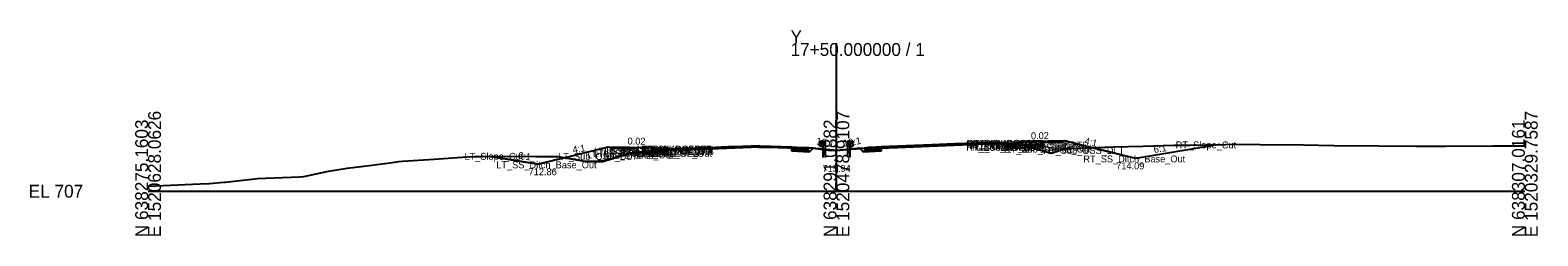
# Model space of a CAD drawing. Extents: x -26 to 303, y -10 to 5039.
# Drawn here: x -25.7 to 302.8, y 990.3 to 1035 of the extents above; entities that cross this region are included whole.
import ezdxf

# ---------------------------------------------------------------- set-up
doc = ezdxf.new("R2010")
doc.units = 0
for name, color, linetype in [('Default', 7, 'Continuous'), ('Exist Cross Section Cell', 7, 'Continuous'), ('Exist XS Center Line Elevation Label', 7, 'Continuous'), ('Exist XS Ground Line', 7, 'Continuous'), ('Prop CMT Pvmt Course 1', 7, 'Continuous'), ('Prop CMT Pvmt Course 2', 7, 'Continuous'), ('Prop CMT Pvmt Course 3', 7, 'Continuous'), ('Prop CMT Pvmt Surface', 7, 'Continuous'), ('Prop CMT Pvmt Surface Shoulder', 7, 'Continuous'), ('Prop CMT Shld Paved Course 1', 7, 'Continuous'), ('Prop CMT Shld Paved Course 2', 7, 'Continuous'), ('Prop CMT Shld Paved Course 3', 7, 'Continuous'), ('Prop CMT Slope Grass', 7, 'Continuous'), ('Prop CMT Subgrade Earthwork', 7, 'Continuous'), ('Prop Conc 4in Sidewalk', 7, 'Continuous'), ('Prop XS Ditch Standard Text', 7, 'Continuous'), ('Prop XS Earthwork Shape', 7, 'Continuous'), ('Prop XS Side Slope Text', 7, 'Continuous'), ('Scratch_Level_0', 7, 'Continuous'), ('Typical Curb CELL', 7, 'Continuous'), ('Typical Guardrail CELL', 7, 'Continuous'), ('Typical Shoulder Slope Information CELL', 7, 'Continuous')]:
    doc.layers.add(name, color=color, linetype=linetype)

# ---------------------------------------------------------------- blocks, each defined once
blk = doc.blocks.new('2_6 CURB RIGHT')
at = {"layer": 'Typical Curb CELL'}
for p, q in [((0, -0.58), (0, 0)), ((0, 0), (1.75, -0.07)), ((2, 0.17), (2, 0.18)), ((2.5, 0.42), (2.24, 0.42)), ((2.31, 0.08), (2.33, -0.01)), ((2.46, 0.04), (2.31, 0.08)), ((2.33, -0.01), (2.46, 0.04)), ((2.5, -0.58), (2.5, 0.42)), ((2.5, -0.58), (0, -0.58)), ((0.26, -0.34), (0.35, -0.22)), ((0.38, -0.34), (0.26, -0.34)), ((0.35, -0.22), (0.38, -0.34)), ((1.03, -0.39), (1.09, -0.28)), ((1.19, -0.36), (1.03, -0.39)), ((1.09, -0.28), (1.19, -0.36)), ((1.51, -0.34), (1.6, -0.22)), ((1.63, -0.34), (1.51, -0.34)), ((1.6, -0.22), (1.63, -0.34)), ((2.27, -0.39), (2.34, -0.28)), ((2.44, -0.36), (2.27, -0.39)), ((2.34, -0.28), (2.44, -0.36))]:
    blk.add_line(p, q, dxfattribs=at)
for centre in [(2.27, 0.34), (2.43, 0.12), (2.49, 0.31), (0.01, -0.55), (0.02, -0.25), (0.03, -0.15), (0.07, -0.39), (0.09, -0.18), (0.17, -0.34), (0.2, -0.06), (0.22, -0.58), (0.3, -0.14), (0.34, -0.04), (0.38, -0.51), (0.49, -0.1), (0.52, -0.21), (0.59, -0.53), (0.67, -0.29), (0.69, -0.12), (0.7, -0.45), (0.71, -0.07), (0.76, -0.56), (0.79, -0.26), (0.93, -0.5), (0.97, -0.1), (1.09, -0.15), (1.11, -0.54), (1.26, -0.55), (1.27, -0.25), (1.28, -0.15), (1.32, -0.39), (1.34, -0.18), (1.42, -0.34), (1.45, -0.1), (1.47, -0.58), (1.54, -0.14), (1.63, -0.51), (1.74, -0.1), (1.77, -0.21), (1.84, -0.53), (1.92, -0.29), (1.94, -0.12), (1.95, -0.45), (1.96, -0.07), (2.01, -0.56), (2.04, -0.26), (2.18, -0.5), (2.22, -0.1), (2.34, -0.15), (2.35, -0.54)]:
    blk.add_circle(centre, 0.00802, dxfattribs=at)
for centre, start, end in [((1.76, 0.17), 267.6155, 0), ((2.24, 0.18), 90, 180)]:
    blk.add_arc(centre, 0.24, start, end, dxfattribs=at)

msp = doc.modelspace()

# ---------------------------------------------------------------- linework, layer by layer
at = {"layer": 'Exist Cross Section Cell'}
for p, q in [((150, 1000), (150, 1032.23)), ((0, 1000), (150, 1000)), ((150, 1000), (300, 1000))]:
    msp.add_line(p, q, dxfattribs=at)
at = {"layer": 'Exist XS Ground Line'}
msp.add_lwpolyline([(0, 1001.13), (11.32, 1001.62), (13.39, 1001.69), (16.48, 1001.95), (16.86, 1001.98), (23.3, 1002.71), (23.79, 1002.76), (33, 1003.14), (33.92, 1003.18), (39.29, 1004.39), (43.39, 1004.99), (46.42, 1005.39), (52.17, 1006.11), (54.68, 1006.47), (55.45, 1006.53), (62.37, 1006.98), (69.47, 1007.46), (71, 1007.58), (73.03, 1007.58), (78.32, 1007.61), (84.6, 1007.54), (89.39, 1007.52), (93.79, 1006.76), (95.25, 1006.5), (96.1, 1006.47), (99.1, 1006.49), (102.64, 1007.54), (104.42, 1008.15), (106.25, 1008.4), (110.51, 1008.99), (111.2, 1009.02), (112.34, 1009.06), (112.69, 1009.07), (114.56, 1009.17), (114.9, 1009.17), (117.35, 1009.26), (117.71, 1009.28), (119.87, 1009.36), (120.52, 1009.39), (122.37, 1009.46), (123.87, 1009.52), (124.88, 1009.56), (126.32, 1009.63), (126.93, 1009.65), (128.26, 1009.64), (129.89, 1009.64), (131.76, 1009.63), (132.42, 1009.63), (132.94, 1009.62), (135.23, 1009.6), (137.49, 1009.58), (139.15, 1009.56), (142.59, 1009.45), (144.9, 1009.37), (147.17, 1009.11), (148.87, 1008.87), (150, 1008.94), (153.3, 1009.16), (155.34, 1009.32), (157.77, 1009.45), (161.68, 1009.64), (162.06, 1009.65), (162.83, 1009.67), (165.12, 1009.78), (165.57, 1009.8), (167.64, 1009.91), (168.37, 1009.95), (170.15, 1010.04), (171.19, 1010.1), (172.65, 1010.18), (173.3, 1010.21), (173.72, 1010.24), (174.51, 1010.25), (175.15, 1010.26), (176.79, 1010.3), (177.66, 1010.32), (179.6, 1010.36), (180.16, 1010.38), (182.69, 1010.42), (184.87, 1010.46), (185.21, 1010.46), (185.63, 1010.46), (186.94, 1010.32), (190.71, 1009.96), (194.45, 1008.93), (196.77, 1008.25), (199.38, 1009.12), (199.69, 1009.21), (201.04, 1009.27), (210.39, 1009.68), (216.83, 1009.82), (223.55, 1009.99), (227.07, 1010.01), (238.79, 1010.23), (242.36, 1010.19), (251.76, 1010.07), (258.37, 1009.98), (268.19, 1009.9), (276.26, 1009.83), (282.7, 1009.81), (293.04, 1009.84), (298.39, 1009.84), (300, 1009.84)], dxfattribs=at)
at = {"layer": 'Prop CMT Pvmt Course 1'}
for points in [[(113.25, 1009.11), (113.25, 1008.87)], [(113.25, 1008.87), (113.26, 1008.87)], [(113.26, 1008.87), (113.26, 1009.11)], [(114, 1009.14), (113.99, 1009.14)], [(113.99, 1008.89), (114, 1008.89)], [(140.25, 1009.39), (140.25, 1009.64)], [(159.75, 1009.39), (159.75, 1009.64)], [(161.93, 1009.47), (161.94, 1009.47)], [(186.74, 1010.14), (186.74, 1010.39)]]:
    msp.add_lwpolyline(points, dxfattribs=at)
at = {"layer": 'Prop CMT Pvmt Course 2'}
for points in [[(113.26, 1008.87), (113.25, 1008.87)], [(113.25, 1008.87), (113.25, 1008.62)], [(113.25, 1008.62), (113.26, 1008.62)], [(113.26, 1008.62), (113.26, 1008.87)], [(114, 1008.89), (113.99, 1008.89)], [(140.25, 1009.14), (140.25, 1009.39)], [(159.75, 1009.14), (159.75, 1009.39)], [(161.94, 1009.47), (161.93, 1009.47)]]:
    msp.add_lwpolyline(points, dxfattribs=at)
at = {"layer": 'Prop CMT Pvmt Course 3'}
for points in [[(113.26, 1008.62), (113.25, 1008.62)], [(113.25, 1008.62), (113.25, 1008.25)], [(113.26, 1008.25), (113.26, 1008.62)], [(140.25, 1008.76), (140.25, 1009.14)], [(140.26, 1008.76), (140.25, 1008.76)], [(159.74, 1008.76), (159.75, 1008.76)], [(159.75, 1008.76), (159.75, 1009.14)], [(113.25, 1008.25), (113.26, 1008.25)]]:
    msp.add_lwpolyline(points, dxfattribs=at)
at = {"layer": 'Prop CMT Pvmt Surface'}
msp.add_lwpolyline([(114, 1009.14), (113.99, 1009.14)], dxfattribs=at)
at = {"layer": 'Prop CMT Pvmt Surface Shoulder'}
for points in [[(133.29, 1009.91), (112.25, 1009.07)], [(133.29, 1009.91), (143.25, 1009.52)], [(182.68, 1010.55), (156.75, 1009.52)], [(182.68, 1010.55), (187.75, 1010.35)]]:
    msp.add_lwpolyline(points, dxfattribs=at)
at = {"layer": 'Prop CMT Shld Paved Course 1'}
for p, q in [((133.28, 1009.66), (143.24, 1009.27)), ((143.51, 1009.26), (143.25, 1009.52)), ((156.49, 1009.26), (156.75, 1009.52)), ((182.68, 1010.3), (187.75, 1010.1))]:
    msp.add_line(p, q, dxfattribs=at)
for points in [[(113.99, 1009.14), (112.25, 1009.07)], [(112.25, 1008.83), (113.26, 1008.87)], [(113.25, 1008.87), (113.25, 1009.11)], [(113.26, 1008.86), (133.28, 1009.66)], [(159.69, 1009.38), (182.68, 1010.3)], [(161.95, 1009.72), (159.95, 1009.64), (159.69, 1009.38)], [(187.75, 1010.1), (186.75, 1010.14)]]:
    msp.add_lwpolyline(points, dxfattribs=at)
at = {"layer": 'Prop CMT Shld Paved Course 2'}
for p, q in [((143.77, 1009), (143.51, 1009.26)), ((156.23, 1009), (156.49, 1009.26))]:
    msp.add_line(p, q, dxfattribs=at)
for points in [[(113.26, 1008.87), (112.25, 1008.83)], [(112.25, 1008.58), (113.26, 1008.62)], [(113.25, 1008.62), (113.25, 1008.87)], [(140.25, 1009.39), (143.51, 1009.26)], [(143.77, 1009), (140.25, 1009.14)], [(156.23, 1009), (159.75, 1009.14)], [(159.75, 1009.39), (156.49, 1009.26)], [(186.75, 1010.14), (187.75, 1010.1)], [(187.75, 1009.85), (186.75, 1009.89)]]:
    msp.add_lwpolyline(points, dxfattribs=at)
at = {"layer": 'Prop CMT Shld Paved Course 3'}
for p, q in [((144.16, 1008.6), (143.77, 1009)), ((155.84, 1008.6), (156.23, 1009)), ((109.25, 1008.5), (108.82, 1008.07)), ((109.75, 1008.5), (109.25, 1008.5))]:
    msp.add_line(p, q, dxfattribs=at)
for points in [[(113.26, 1008.62), (112.25, 1008.58)], [(113.25, 1008.25), (113.25, 1008.62)], [(140.25, 1009.14), (143.77, 1009)], [(144.16, 1008.6), (140.25, 1008.76)], [(155.84, 1008.6), (159.75, 1008.76)], [(159.75, 1009.14), (156.23, 1009)], [(186.75, 1009.89), (187.75, 1009.85)], [(191.18, 1009.34), (186.75, 1009.52)], [(108.82, 1008.07), (113.26, 1008.25)]]:
    msp.add_lwpolyline(points, dxfattribs=at)
at = {"layer": 'Prop CMT Slope Grass'}
for p, q in [((84.97, 1005.86), (100.25, 1009.68)), ((100.25, 1009.68), (109.75, 1009.49)), ((150, 1008.84), (143.25, 1009.52)), ((150, 1008.84), (156.75, 1009.52)), ((199.75, 1010.96), (190.25, 1010.77)), ((215.23, 1007.09), (199.75, 1010.96)), ((233.51, 1010.13), (215.23, 1007.09)), ((74.6, 1007.59), (84.97, 1005.86))]:
    msp.add_line(p, q, dxfattribs=at)
at = {"layer": 'Prop CMT Subgrade Earthwork'}
for p, q in [((108.82, 1008.07), (107.35, 1009.54)), ((113.26, 1008.25), (113.26, 1009.11)), ((140.25, 1009.64), (140.25, 1008.76)), ((159.75, 1009.64), (159.75, 1008.76)), ((191.18, 1009.34), (192.65, 1010.82))]:
    msp.add_line(p, q, dxfattribs=at)
for points in [[(140.25, 1009.64), (140.25, 1008.76), (140.26, 1008.76)], [(140.25, 1008.76), (144.16, 1008.6)], [(144.16, 1008.6), (144.91, 1009.35)], [(155.84, 1008.6), (155.09, 1009.35)], [(159.75, 1008.76), (155.84, 1008.6)], [(159.75, 1009.64), (159.75, 1008.76), (159.74, 1008.76)], [(186.74, 1010.39), (186.74, 1009.52), (186.75, 1009.52)], [(186.75, 1009.52), (191.18, 1009.34)], [(113.26, 1008.25), (108.82, 1008.07)]]:
    msp.add_lwpolyline(points, dxfattribs=at)
at = {"layer": 'Prop Conc 4in Sidewalk'}
for p, q in [((100.75, 1009.67), (100.75, 1009.34)), ((100.75, 1009.34), (105.75, 1009.24)), ((105.75, 1009.57), (105.75, 1009.24)), ((194.25, 1010.85), (194.25, 1010.51)), ((199.25, 1010.61), (194.25, 1010.51)), ((199.25, 1010.95), (199.25, 1010.61))]:
    msp.add_line(p, q, dxfattribs=at)
at = {"layer": 'Prop XS Earthwork Shape'}
for points in [[(100.25, 1009.68), (107.35, 1009.54), (108.22, 1008.67), (106.25, 1008.4), (104.42, 1008.15), (102.64, 1007.54), (99.1, 1006.49), (96.1, 1006.47), (95.25, 1006.5), (93.79, 1006.76), (90.7, 1007.29)], [(110.51, 1008.99), (111.2, 1009.02), (112.34, 1009.06), (112.69, 1009.07), (113.26, 1009.11), (113.26, 1008.25), (108.82, 1008.07), (108.22, 1008.67)], [(114.67, 1009.17), (113.26, 1009.11), (114.56, 1009.17)], [(140.25, 1009.64), (140.25, 1009.52), (139.15, 1009.56), (137.49, 1009.58), (135.23, 1009.6), (132.94, 1009.62), (132.42, 1009.63), (131.76, 1009.63), (129.89, 1009.64), (128.26, 1009.64), (126.93, 1009.65), (126.32, 1009.63), (124.88, 1009.56), (123.87, 1009.52), (122.37, 1009.46), (120.52, 1009.39), (119.87, 1009.36), (117.71, 1009.28), (117.35, 1009.26), (114.9, 1009.17), (114.67, 1009.17), (133.29, 1009.91)], [(140.25, 1009.52), (140.26, 1008.76), (144.16, 1008.6), (144.91, 1009.35), (144.6, 1009.38), (142.59, 1009.45)], [(144.91, 1009.35), (144.6, 1009.38), (144.9, 1009.37), (146.08, 1009.23)], [(148.87, 1008.87), (149.39, 1008.9), (146.08, 1009.23), (147.17, 1009.11)], [(150, 1008.94), (153.11, 1009.15), (150, 1008.84), (149.39, 1008.9)], [(155.14, 1009.31), (155.09, 1009.35), (153.11, 1009.15), (153.3, 1009.16)], [(155.14, 1009.31), (155.34, 1009.32), (157.77, 1009.45), (159.75, 1009.55), (159.74, 1008.76), (155.84, 1008.6)], [(170.15, 1010.04), (170.77, 1010.08), (159.75, 1009.64), (159.75, 1009.55), (161.68, 1009.64), (162.06, 1009.65), (162.83, 1009.67), (165.12, 1009.78), (165.57, 1009.8), (167.64, 1009.91), (168.37, 1009.95)], [(175.15, 1010.26), (175.79, 1010.28), (170.77, 1010.08), (171.19, 1010.1), (172.65, 1010.18), (173.3, 1010.21), (173.72, 1010.24), (174.51, 1010.25)], [(182.68, 1010.55), (175.79, 1010.28), (176.79, 1010.3), (177.66, 1010.32), (179.6, 1010.36), (180.16, 1010.38), (182.69, 1010.42), (184.87, 1010.46), (185.07, 1010.46)], [(185.07, 1010.46), (186, 1010.42), (185.63, 1010.46), (185.21, 1010.46)], [(186.74, 1010.39), (186.74, 1010.34), (186, 1010.42)], [(186.74, 1010.34), (186.94, 1010.32), (190.71, 1009.96), (191.56, 1009.72), (191.18, 1009.34), (186.75, 1009.52)], [(194.45, 1008.93), (196.77, 1008.25), (199.38, 1009.12), (199.69, 1009.21), (201.04, 1009.27), (205.68, 1009.47), (199.75, 1010.96), (192.65, 1010.82), (191.56, 1009.72)], [(233.51, 1010.13), (215.23, 1007.09), (205.68, 1009.47), (210.39, 1009.68), (216.83, 1009.82), (223.55, 1009.99), (227.07, 1010.01)], [(74.6, 1007.59), (78.32, 1007.61), (84.6, 1007.54), (89.39, 1007.52), (90.7, 1007.29), (84.97, 1005.86)]]:
    msp.add_lwpolyline(points, close=True, dxfattribs=at)
at = {"layer": 'Typical Guardrail CELL'}
for p, q in [((146.57, 1010.86), (146.28, 1010.66)), ((146.57, 1010.33), (146.28, 1010.53)), ((146.57, 1010.23), (146.28, 1010.03)), ((146.57, 1009.7), (146.28, 1009.9)), ((147.07, 1010.86), (146.57, 1010.86)), ((146.57, 1010.86), (146.57, 1009.7)), ((146.57, 1010.28), (146.57, 1010.33)), ((146.57, 1010.28), (146.57, 1010.23)), ((147.07, 1009.7), (146.57, 1009.7)), ((147.07, 1010.86), (147.07, 1008.38)), ((147.07, 1010.86), (147.57, 1010.86)), ((147.57, 1010.86), (147.57, 1008.38)), ((152.93, 1010.9), (152.43, 1010.9)), ((152.43, 1010.9), (152.43, 1008.41)), ((152.93, 1010.9), (152.93, 1008.41)), ((152.93, 1010.9), (153.43, 1010.9)), ((152.93, 1009.74), (153.43, 1009.74)), ((153.43, 1010.9), (153.43, 1009.74)), ((153.43, 1010.9), (153.72, 1010.7)), ((153.43, 1010.37), (153.72, 1010.57)), ((153.43, 1010.32), (153.43, 1010.37)), ((153.43, 1010.32), (153.43, 1010.27)), ((153.43, 1010.27), (153.72, 1010.07)), ((153.43, 1009.74), (153.72, 1009.94)), ((147.07, 1008.38), (147.57, 1008.38)), ((147.07, 1008.38), (147.07, 1007.37)), ((147.57, 1008.38), (147.57, 1007.37)), ((152.93, 1008.41), (152.43, 1008.41)), ((152.43, 1008.41), (152.43, 1007.41)), ((152.93, 1008.41), (152.93, 1007.41))]:
    msp.add_line(p, q, dxfattribs=at)
for centre, start, end in [((146.33, 1010.59), 125.003, 235.0112), ((146.33, 1009.97), 125.0059, 235.0366), ((153.67, 1010.63), 304.9888, 54.997), ((153.67, 1010.01), 304.9634, 54.9941)]:
    msp.add_arc(centre, 0.0776, start, end, dxfattribs=at)

# ---------------------------------------------------------------- block references
at = {"layer": 'Prop CMT Slope Grass', "yscale": -1, "rotation": 180}
msp.add_blockref('2_6 CURB RIGHT', (112.25, 1009.07), dxfattribs=at)
at = {"layer": 'Prop CMT Slope Grass'}
msp.add_blockref('2_6 CURB RIGHT', (187.75, 1010.35), dxfattribs=at)

# ---------------------------------------------------------------- texts
at = {"layer": 'Default'}
msp.add_text('-', height=0.0001, dxfattribs=at).set_placement((0, 1000))
at = {"layer": 'Exist Cross Section Cell'}
for s, p in [('Y', (140, 1032.23)), ('17+50.000000 / 1', (140, 1029.43)), ('EL 707', (-26, 998.6))]:
    msp.add_text(s, height=2.8, dxfattribs=at).set_placement(p)
for s, p in [('N 638275.1603', (0, 990)), ('E 1520628.0626', (2.8, 990)), ('N 638291.0882', (150, 990)), ('E 1520478.9107', (152.8, 990)), ('N 638307.0161', (300, 990)), ('E 1520329.7587', (302.8, 990))]:
    msp.add_text(s, height=2.8, rotation=90, dxfattribs=at).set_placement(p)
at = {"layer": 'Exist XS Center Line Elevation Label'}
msp.add_text('715.94', height=1.5, dxfattribs=at).set_placement((146.97, 1004.19))
at = {"layer": 'Prop XS Ditch Standard Text'}
for s, p in [('714.09', (210.96, 1004.77)), ('712.86', (82.92, 1003.49))]:
    msp.add_text(s, height=1.5, dxfattribs=at).set_placement(p)
at = {"layer": 'Prop XS Side Slope Text'}
for s, rotation, p in [('4:1', 9.4623, (92.63, 1008.25)), ('10:1', 350.5377, (145.51, 1010.21)), ('10:1', 9.4623, (151.61, 1009.67)), ('4:1', 346.7942, (203.91, 1010.26)), ('6:1', 9.4809, (219.26, 1008.29)), ('6:1', 350.5191, (80.53, 1007.15))]:
    msp.add_text(s, height=1.5, rotation=rotation, dxfattribs=at).set_placement(p)
at = {"layer": 'Scratch_Level_0'}
for s, p in [('LT_Sub_Trench_Out', (95.74, 1007.14)), ('LT_PS3_Shelf_Out', (96.95, 1007.53)), ('LT_GS_OS_CTL', (97.19, 1007.99)), ('LT_PS3_OEOP', (99.15, 1007.55)), ('LT_PS2_OEOP', (99.41, 1007.81)), ('LT_PS1_OEOP', (99.85, 1008.07)), ('LT_PV2_PGL_Out', (106.36, 1008.14)), ('LT_PV3_PGL_Out', (106.36, 1007.89)), ('LT_Sub_PGL_Out', (106.4, 1007.52)), ('LT_Sub_Out_DLT', (106.49, 1008.39)), ('LT_PV1_PGL_Out', (106.54, 1008.39)), ('LT_PV2_OEOT', (107.61, 1008.14)), ('LT_PV3_OEOT', (107.61, 1007.89)), ('LT_Sub_OEOT', (107.64, 1007.52)), ('LT_PV1_OEOT', (107.79, 1008.39)), ('RT_PV2_PGL_Out', (178.27, 1009.42)), ('RT_PV3_PGL_Out', (178.27, 1009.17)), ('RT_Sub_PGL_Out', (178.31, 1008.8)), ('RT_Sub_Out_DLT', (178.37, 1009.67)), ('RT_PV1_PGL_Out', (178.45, 1009.67)), ('RT_PV2_OEOT', (179.54, 1009.42)), ('RT_PV3_OEOT', (179.54, 1009.17)), ('RT_Sub_OEOT', (179.57, 1008.8)), ('RT_PV1_OEOT', (179.72, 1009.67)), ('RT_Sub_Trench_Out', (186.5, 1008.42)), ('RT_PS3_Shelf_Out', (186.93, 1008.81)), ('RT_PS1_OEOP', (187.78, 1009.35)), ('RT_PS2_OEOP', (187.86, 1009.09)), ('RT_PS3_OEOP', (188.12, 1008.83)), ('RT_GS_OS_CTL', (189.12, 1009.27)), ('RT_Sub_OSS_DLT', (195.1, 1008.12)), ('RT_Slope_Cut', (223.93, 1009.32)), ('LT_Slope_Cut', (68.94, 1006.84)), ('LT_SS_Ditch_Base_Out', (75.88, 1004.99)), ('LT_Sub_OSS_DLT', (89.35, 1006.84)), ('RT_SS_Ditch_Base_Out', (203.81, 1006.27))]:
    msp.add_text(s, height=1.5, dxfattribs=at).set_placement(p)
at = {"layer": 'Typical Shoulder Slope Information CELL'}
for rotation, p in [(1.1403, (192.4, 1011.3)), (358.8597, (104.48, 1010.18))]:
    msp.add_text('0.02', height=1.5, rotation=rotation, dxfattribs=at).set_placement(p)

doc.saveas('drawing.dxf')
